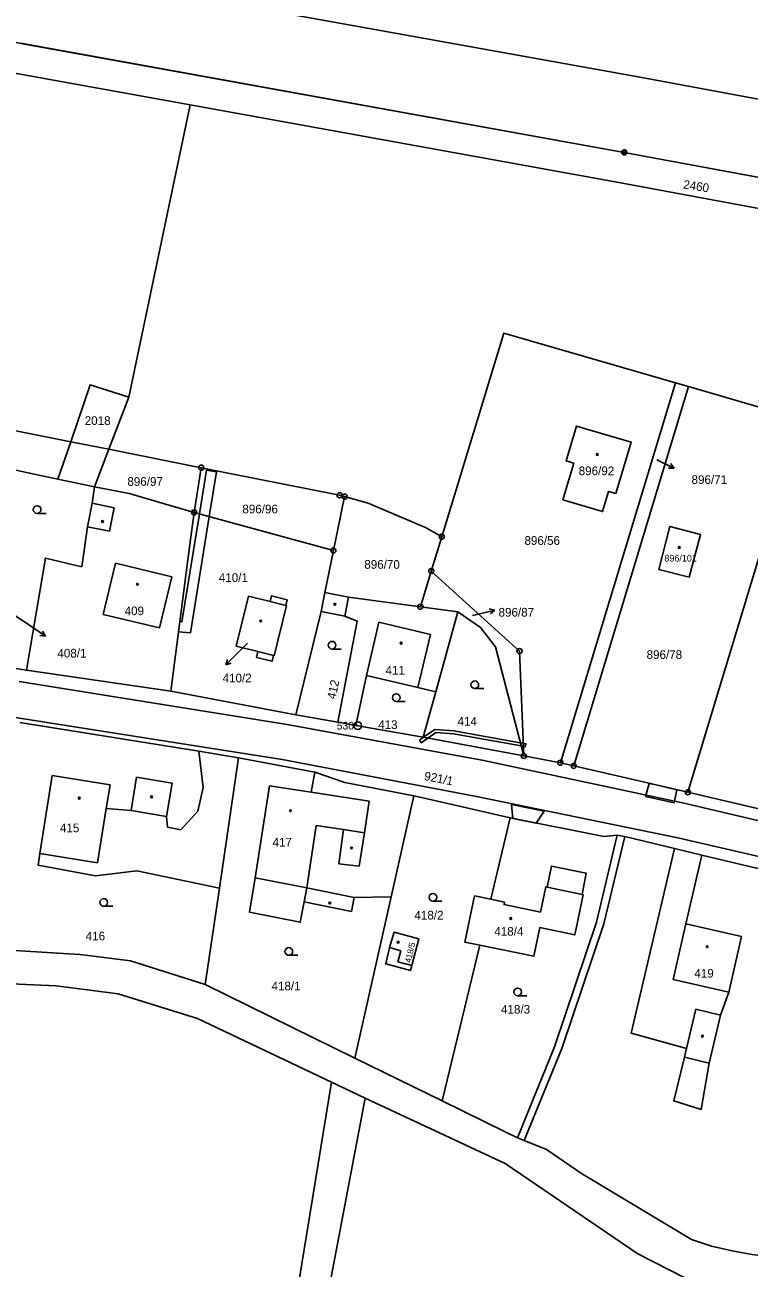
# Model space of a CAD drawing. Extents: x -504988 to -494607, y -1123820 to -1114018.
# Drawn here: x -500513.4 to -500371.7, y -1121156.5 to -1120913.2 of the extents above; entities that cross this region are included whole.
import ezdxf

# ---------------------------------------------------------------- set-up
doc = ezdxf.new("R2010")
doc.units = 0
for name, color, linetype in [('Hranice parcel', 7, 'Continuous'), ('Parcelní čísla', 7, 'Continuous'), ('Pop  PČ popisy', 7, 'Continuous'), ('Poz předměty', 7, 'Continuous'), ('Vnitřní kresba', 7, 'Continuous'), ('Věcná břemena k části', 7, 'Continuous'), ('Značky bodu BP', 7, 'Continuous'), ('Značky budov', 7, 'Continuous'), ('Značky kultur', 7, 'Continuous')]:
    doc.layers.add(name, color=color, linetype=linetype)

msp = doc.modelspace()

# ---------------------------------------------------------------- linework, layer by layer
at = {"layer": 'Hranice parcel'}
for p, q in [((-500493.12, -1120986.11), (-500481.13, -1120928.92)), ((-500386.18, -1120983.28), (-500408.67, -1121057.62)), ((-500383.63, -1120984.02), (-500386.18, -1120983.28)), ((-500497.01, -1120996.29), (-500493.12, -1120986.11)), ((-500406.06, -1121058.23), (-500383.63, -1120984.02)), ((-500361.67, -1120990.39), (-500383.63, -1120984.02)), ((-500383.73, -1121063.41), (-500361.67, -1120990.39)), ((-500504.48, -1120994.81), (-500506.98, -1121002.13)), ((-500504.48, -1120994.81), (-500497.01, -1120996.29)), ((-500499.83, -1121003.66), (-500497.01, -1120996.29)), ((-500478.93, -1120999.89), (-500497.01, -1120996.29)), ((-500478.93, -1120999.89), (-500480.34, -1121008.65)), ((-500450.89, -1121005.56), (-500453.08, -1121016.1)), ((-500446.3, -1121006.85), (-500450.89, -1121005.56)), ((-500453.08, -1121016.1), (-500480.34, -1121008.65)), ((-500431.88, -1121013.39), (-500433.93, -1121020.12)), ((-500454.75, -1121024.31), (-500453.08, -1121016.1)), ((-500433.93, -1121020.12), (-500436.05, -1121027.1)), ((-500433.93, -1121020.12), (-500416.66, -1121035.78)), ((-500455.46, -1121028.02), (-500454.75, -1121024.31)), ((-500436.05, -1121027.1), (-500428.72, -1121028.09)), ((-500460.42, -1121048.25), (-500455.46, -1121028.02)), ((-500433.07, -1121043.73), (-500428.72, -1121028.09)), ((-500415.85, -1121056.28), (-500421.36, -1121034.93)), ((-500416.66, -1121035.78), (-500415.85, -1121056.28)), ((-500513.13, -1121039.51), (-500521.79, -1121038.18)), ((-500513.13, -1121039.51), (-500484.9, -1121043.64)), ((-500484.9, -1121043.64), (-500460.42, -1121048.25)), ((-500435.55, -1121052.61), (-500433.07, -1121043.73)), ((-500460.42, -1121048.25), (-500452.18, -1121049.69)), ((-500479.4, -1121055.39), (-500514.41, -1121049.75)), ((-500452.18, -1121049.69), (-500448.67, -1121050.31)), ((-500448.67, -1121050.31), (-500435.55, -1121052.61)), ((-500435.55, -1121052.61), (-500415.85, -1121056.28)), ((-500471.62, -1121056.64), (-500479.4, -1121055.39)), ((-500475.37, -1121082.19), (-500471.62, -1121056.64)), ((-500456.69, -1121059.44), (-500471.62, -1121056.64)), ((-500408.67, -1121057.62), (-500415.85, -1121056.28)), ((-500408.67, -1121057.62), (-500406.06, -1121058.23)), ((-500441.77, -1121083.84), (-500437.33, -1121064.12)), ((-500422.29, -1121084.33), (-500418.49, -1121068.4)), ((-500418.49, -1121068.4), (-500400.14, -1121072.06)), ((-500400.14, -1121072.06), (-500397.59, -1121071.79)), ((-500380.99, -1121075.69), (-500386.37, -1121074.4)), ((-500341.82, -1121085.07), (-500380.99, -1121075.69)), ((-500478.14, -1121101.05), (-500475.37, -1121082.19)), ((-500427.34, -1121092.71), (-500425.48, -1121083.68)), ((-500425.48, -1121083.68), (-500422.29, -1121084.33)), ((-500448.9, -1121115.46), (-500441.77, -1121083.84)), ((-500422.29, -1121084.33), (-500419.58, -1121084.88)), ((-500431.83, -1121123.81), (-500424.46, -1121093.31)), ((-500424.46, -1121093.31), (-500427.34, -1121092.71)), ((-500413.87, -1121095.5), (-500424.46, -1121093.31)), ((-500448.9, -1121115.46), (-500431.83, -1121123.81)), ((-500469.81, -1121219.81), (-500453.45, -1121120.1)), ((-500453.45, -1121120.1), (-500446.85, -1121123.24)), ((-500446.85, -1121123.24), (-500465.32, -1121220.56))]:
    msp.add_line(p, q, dxfattribs=at)
for points in [[(-500764.98, -1120898.32), (-500631.41, -1120885.98), (-500618.26, -1120885.7), (-500608.56, -1120886.58), (-500597.08, -1120888.85), (-500587.15, -1120891.94), (-500532.37, -1120912.08), (-500524.35, -1120914.64), (-500516.15, -1120916.5), (-500513.53, -1120917), (-500396.19, -1120938.19), (-500282.34, -1120959.31), (-500275.43, -1120961.08), (-500094.63, -1121020.61), (-499913.83, -1121080.14), (-499909.87, -1121081.53), (-499905.97, -1121083.08), (-499793.8, -1121130.28), (-499791.45, -1121131.2), (-499789.49, -1121131.83)], [(-500481.13, -1120928.92), (-500517.21, -1120922.4), (-500525.93, -1120920.43), (-500534.44, -1120917.72), (-500589.22, -1120897.57), (-500597.01, -1120895.29), (-500604.68, -1120893.47), (-500611.82, -1120892.14), (-500620.47, -1120890.99)], [(-500275.13, -1120945.54), (-500279.36, -1120944.61), (-500393.48, -1120923.43), (-500512.84, -1120901.87), (-500515.38, -1120901.3)], [(-500481.13, -1120928.92), (-500397.25, -1120944.09), (-500283.44, -1120965.21), (-500278.08, -1120966.53), (-500138.09, -1121012.62)], [(-500386.18, -1120983.28), (-500419.74, -1120973.55), (-500431.88, -1121013.39)], [(-500561.67, -1120980.8), (-500539.74, -1120987.79), (-500504.48, -1120994.81)], [(-500504.48, -1120994.81), (-500500.68, -1120983.67), (-500493.12, -1120986.11)], [(-500397.82, -1121004.97), (-500399.24, -1121004.55), (-500400.41, -1121008.49), (-500408.18, -1121006.18), (-500406.07, -1120999), (-500407.51, -1120998.57), (-500405.49, -1120991.74), (-500394.82, -1120994.88), (-500397.82, -1121004.97)], [(-500506.98, -1121002.13), (-500512.53, -1121000.94), (-500516.66, -1121000.06)], [(-500450.89, -1121005.56), (-500451.86, -1121005.28), (-500478.93, -1120999.89)], [(-500499.83, -1121003.66), (-500500.29, -1121006.85), (-500501.21, -1121011.47), (-500502.32, -1121019.29), (-500509.4, -1121017.57), (-500513.13, -1121039.51)], [(-500480.34, -1121008.65), (-500493.03, -1121004.96), (-500499.83, -1121003.66)], [(-500431.88, -1121013.39), (-500434.93, -1121011.64), (-500446.3, -1121006.85)], [(-500484.9, -1121043.64), (-500481.16, -1121014.93), (-500480.34, -1121008.65)], [(-500383.49, -1121021.34), (-500389.44, -1121019.8), (-500387.23, -1121011.39), (-500381.27, -1121012.96), (-500383.49, -1121021.34)], [(-500462.1, -1121025.73), (-500462.37, -1121026.84), (-500462.23, -1121026.88), (-500464.67, -1121036.69), (-500464.8, -1121036.65), (-500465.08, -1121037.77), (-500468.14, -1121037.02), (-500467.87, -1121035.86), (-500472.09, -1121034.84), (-500469.68, -1121025.06), (-500465.44, -1121026.08), (-500465.16, -1121024.95), (-500462.1, -1121025.73)], [(-500436.05, -1121027.1), (-500450.12, -1121025.2), (-500454.75, -1121024.31)], [(-500455.46, -1121028.02), (-500450.82, -1121028.92), (-500448.4, -1121029.91), (-500452.18, -1121049.69)], [(-500421.36, -1121034.93), (-500424.29, -1121031.16), (-500428.72, -1121028.09)], [(-500448.67, -1121050.31), (-500446.61, -1121040.56), (-500436.54, -1121042.92), (-500433.07, -1121043.73)], [(-500479.4, -1121055.39), (-500478.53, -1121062.5), (-500479.58, -1121067.09), (-500482.94, -1121070.75), (-500485.53, -1121070.22), (-500485.71, -1121068.13), (-500484.65, -1121061.59), (-500491.58, -1121060.46), (-500492.64, -1121067), (-500497.52, -1121066.6), (-500496.78, -1121061.97), (-500508.07, -1121060.15), (-500510.53, -1121075.4), (-500510.85, -1121077.64), (-500499.6, -1121079.78), (-500491.56, -1121078.76), (-500475.37, -1121082.19)], [(-500406.06, -1121058.23), (-500389.93, -1121061.97), (-500383.73, -1121063.41)], [(-500456.69, -1121059.44), (-500457.41, -1121063.38), (-500465.55, -1121062.13), (-500468.41, -1121080.12), (-500469.48, -1121086.87), (-500459.55, -1121088.85), (-500458.83, -1121084.85), (-500449.57, -1121086.73), (-500449.01, -1121084), (-500441.77, -1121083.84)], [(-500437.33, -1121064.12), (-500450.85, -1121061.52), (-500456.69, -1121059.44)], [(-500437.33, -1121064.12), (-500435.84, -1121064.41), (-500418.49, -1121068.4)], [(-500383.73, -1121063.41), (-500365.68, -1121067.62), (-500361.28, -1121068.59)], [(-500417.04, -1121131.03), (-500409.84, -1121113.22), (-500401.6, -1121088.85), (-500397.59, -1121071.79)], [(-500386.37, -1121074.4), (-500396.06, -1121072.08), (-500397.59, -1121071.79)], [(-500386.37, -1121074.4), (-500394.82, -1121110.53), (-500384, -1121113.54), (-500384.41, -1121115.22), (-500386.48, -1121123.8), (-500381.12, -1121125.46), (-500379.59, -1121116.38), (-500377.34, -1121107.02), (-500375.74, -1121102.5), (-500373.26, -1121091.63), (-500384.13, -1121089.15), (-500380.99, -1121075.69)], [(-500419.58, -1121084.88), (-500419.68, -1121085.38), (-500412.57, -1121086.84), (-500411.55, -1121081.93), (-500411.28, -1121081.98), (-500410.44, -1121077.85), (-500403.6, -1121079.25), (-500404.43, -1121083.41), (-500404.22, -1121083.45), (-500405.86, -1121091.3), (-500412.7, -1121089.88), (-500413.87, -1121095.5)], [(-500437.75, -1121097.29), (-500438.02, -1121098.29), (-500442.83, -1121096.98), (-500442.08, -1121093.76), (-500441.22, -1121090.81), (-500439.03, -1121091.34), (-500436.34, -1121092.07), (-500437.75, -1121097.29)], [(-500520.79, -1121094.02), (-500502.67, -1121095.18), (-500501.61, -1121095.25), (-500492.78, -1121096.41), (-500478.14, -1121101.05)], [(-500453.45, -1121120.1), (-500479.67, -1121107.66), (-500495.2, -1121102.84), (-500507.32, -1121101.3), (-500520.55, -1121100.68), (-500557.7, -1121101.61), (-500589.02, -1121105.86), (-500602.59, -1121106.82), (-500624.72, -1121106.08), (-500646.33, -1121106.76), (-500655.09, -1121112.32), (-500660.29, -1121119.96), (-500660.92, -1121120.88), (-500668.64, -1121133.13), (-500674.71, -1121144.91), (-500681.84, -1121162.26), (-500689.12, -1121188.67)], [(-500478.14, -1121101.05), (-500452.75, -1121113.56), (-500448.9, -1121115.46)], [(-500093.53, -1121309.79), (-500096.64, -1121297.58), (-500125.14, -1121250.31), (-500143.37, -1121221.49), (-500154.49, -1121207.58), (-500171.25, -1121193.24), (-500179.79, -1121189.25), (-500191.69, -1121184.83), (-500210.15, -1121179.42), (-500240.92, -1121170.5), (-500265.19, -1121164.1), (-500289.32, -1121158.74), (-500305.17, -1121156.16), (-500321.82, -1121158.18), (-500359.14, -1121160.88), (-500369.12, -1121161.84), (-500376.67, -1121161), (-500384.33, -1121158.44), (-500393.5, -1121153.73), (-500419.45, -1121136.05), (-500446.85, -1121123.24)], [(-500431.83, -1121123.81), (-500419.48, -1121129.84), (-500417.04, -1121131.03)], [(-500417.04, -1121131.03), (-500415.78, -1121131.53), (-500411.36, -1121133.29), (-500404.51, -1121137.98), (-500383.05, -1121150.93), (-500379.09, -1121152.23), (-500375.08, -1121153.13), (-500371.2, -1121153.85), (-500367.89, -1121154.23), (-500362.33, -1121154.85), (-500358.56, -1121155.1)]]:
    msp.add_lwpolyline(points, dxfattribs=at)
at = {"layer": 'Pop  PČ popisy'}
for p, q in [((-500389.83, -1120998.31), (-500389.13, -1120998.65)), ((-500389.13, -1120998.65), (-500386.43, -1120999.97)), ((-500386.43, -1120999.97), (-500387.55, -1120999.98)), ((-500386.43, -1120999.97), (-500387.11, -1120999.08)), ((-500421.5, -1121027.8), (-500422.58, -1121027.54)), ((-500515.83, -1121028.51), (-500511.9, -1121031.19)), ((-500425.89, -1121028.82), (-500424.42, -1121028.48)), ((-500424.42, -1121028.48), (-500421.5, -1121027.8)), ((-500421.5, -1121027.8), (-500422.36, -1121028.52)), ((-500511.9, -1121031.19), (-500509.41, -1121032.87)), ((-500509.41, -1121032.87), (-500509.96, -1121031.89)), ((-500509.41, -1121032.87), (-500510.52, -1121032.72)), ((-500469.88, -1121034.25), (-500472.01, -1121036.35)), ((-500472.01, -1121036.35), (-500474.13, -1121038.47)), ((-500474.13, -1121038.47), (-500473.78, -1121037.41)), ((-500474.13, -1121038.47), (-500473.07, -1121038.12))]:
    msp.add_line(p, q, dxfattribs=at)
at = {"layer": 'Poz předměty'}
for p, q in [((-500514.25, -1120916.84), (-500396.18, -1120938.19)), ((-500396.18, -1120938.19), (-500278.83, -1120959.96))]:
    msp.add_line(p, q, dxfattribs=at)
for radius in [0.5, 0.4, 0.3, 0.2, 0.1]:
    msp.add_circle((-500396.18, -1120938.19), radius, dxfattribs=at)
at = {"layer": 'Vnitřní kresba'}
for p, q in [((-500499.83, -1121003.66), (-500506.98, -1121002.13)), ((-500500.29, -1121006.85), (-500495.94, -1121007.72)), ((-500495.94, -1121007.72), (-500496.86, -1121012.34)), ((-500496.86, -1121012.34), (-500501.21, -1121011.47)), ((-500498.11, -1121028.59), (-500495.7, -1121018.59)), ((-500495.7, -1121018.59), (-500484.72, -1121021.24)), ((-500484.72, -1121021.24), (-500487.13, -1121031.23)), ((-500450.12, -1121025.2), (-500450.82, -1121028.92)), ((-500465.44, -1121026.08), (-500462.37, -1121026.84)), ((-500487.13, -1121031.23), (-500498.11, -1121028.59)), ((-500446.61, -1121040.56), (-500444.18, -1121030.15)), ((-500444.18, -1121030.15), (-500434.11, -1121032.51)), ((-500434.11, -1121032.51), (-500436.54, -1121042.92)), ((-500467.87, -1121035.86), (-500464.8, -1121036.65)), ((-500514.53, -1121041.74), (-500462.1, -1121050.16)), ((-500463.1, -1121056.99), (-500516.96, -1121048.51)), ((-500462.1, -1121050.16), (-500423.67, -1121057.16)), ((-500425.1, -1121064.21), (-500463.1, -1121056.99)), ((-500423.67, -1121057.16), (-500384.2, -1121065.61)), ((-500457.41, -1121063.38), (-500446.05, -1121065.12)), ((-500385.7, -1121072.34), (-500425.1, -1121064.21)), ((-500497.52, -1121066.6), (-500499.23, -1121077.22)), ((-500446.05, -1121065.12), (-500447.01, -1121071.31)), ((-500384.2, -1121065.61), (-500347.24, -1121074.26)), ((-500485.71, -1121068.13), (-500492.64, -1121067)), ((-500456.42, -1121069.91), (-500458.28, -1121082.13)), ((-500451.11, -1121070.7), (-500456.42, -1121069.91)), ((-500451.99, -1121077.39), (-500451.11, -1121070.7)), ((-500447.01, -1121071.31), (-500451.11, -1121070.7)), ((-500447.01, -1121071.31), (-500448.02, -1121077.88)), ((-500396.06, -1121072.08), (-500400.18, -1121089.15)), ((-500348.68, -1121080.83), (-500385.7, -1121072.34)), ((-500499.23, -1121077.22), (-500510.53, -1121075.4)), ((-500448.02, -1121077.88), (-500451.99, -1121077.39)), ((-500458.28, -1121082.13), (-500468.41, -1121080.12)), ((-500458.83, -1121084.85), (-500458.28, -1121082.13)), ((-500458.28, -1121082.13), (-500449.01, -1121084)), ((-500411.28, -1121081.98), (-500404.43, -1121083.41)), ((-500400.18, -1121089.15), (-500408.42, -1121113.53)), ((-500386.61, -1121100.02), (-500384.13, -1121089.15)), ((-500442.08, -1121093.76), (-500439.91, -1121094.4)), ((-500439.91, -1121094.4), (-500440.45, -1121096.56)), ((-500440.45, -1121096.56), (-500437.75, -1121097.29)), ((-500375.74, -1121102.5), (-500386.61, -1121100.02)), ((-500384, -1121113.54), (-500382.15, -1121105.86)), ((-500382.15, -1121105.86), (-500377.34, -1121107.02)), ((-500408.42, -1121113.53), (-500415.78, -1121131.53)), ((-500379.59, -1121116.38), (-500384.41, -1121115.22))]:
    msp.add_line(p, q, dxfattribs=at)
at = {"layer": 'Věcná břemena k části'}
for points in [[(-500477.92, -1121000.38), (-500479.3, -1121008.93), (-500482.73, -1121030.06), (-500483.13, -1121030.02), (-500483.38, -1121032.01), (-500481.05, -1121032.22), (-500477.36, -1121009.46), (-500475.94, -1121000.7)], [(-500435.42, -1121052.63), (-500434.59, -1121052.79), (-500433.04, -1121051.72), (-500429.56, -1121051.95), (-500416.35, -1121054.35), (-500415.92, -1121054.43), (-500415.95, -1121053.82), (-500416.51, -1121053.71), (-500429.49, -1121051.35), (-500433.21, -1121051.11)], [(-500436.24, -1121053.21), (-500435.9, -1121053.7), (-500434.59, -1121052.79), (-500435.42, -1121052.63)], [(-500415.92, -1121054.43), (-500415.54, -1121054.5), (-500415.43, -1121053.91), (-500415.95, -1121053.82)], [(-500391.99, -1121064.25), (-500386.43, -1121065.47), (-500385.9, -1121062.91), (-500389.93, -1121061.97), (-500391.28, -1121061.66)], [(-500417.95, -1121068.51), (-500413.4, -1121069.42), (-500411.86, -1121067.07), (-500418.23, -1121065.77)]]:
    msp.add_lwpolyline(points, close=True, dxfattribs=at)
at = {"layer": 'Značky bodu BP'}
for centre, radius in [((-500478.93, -1120999.89), 0.5), ((-500478.93, -1120999.89), 0.0303), ((-500451.86, -1121005.28), 0.5), ((-500451.86, -1121005.28), 0.0303), ((-500450.89, -1121005.56), 0.5), ((-500450.89, -1121005.56), 0.0303), ((-500480.34, -1121008.65), 0.5), ((-500480.34, -1121008.65), 0.0303), ((-500431.88, -1121013.39), 0.5), ((-500453.08, -1121016.1), 0.5), ((-500431.88, -1121013.39), 0.0303), ((-500453.08, -1121016.1), 0.0303), ((-500433.93, -1121020.12), 0.5), ((-500433.93, -1121020.12), 0.0303), ((-500436.05, -1121027.1), 0.5), ((-500436.05, -1121027.1), 0.0303), ((-500416.66, -1121035.78), 0.5), ((-500416.66, -1121035.78), 0.0303), ((-500448.31, -1121050.37), 0.75), ((-500448.31, -1121050.37), 0.03), ((-500415.85, -1121056.28), 0.5), ((-500415.85, -1121056.28), 0.0303), ((-500408.67, -1121057.62), 0.5), ((-500408.67, -1121057.62), 0.0303), ((-500406.06, -1121058.23), 0.5), ((-500406.06, -1121058.23), 0.0303), ((-500383.73, -1121063.41), 0.5), ((-500383.73, -1121063.41), 0.0303)]:
    msp.add_circle(centre, radius, dxfattribs=at)
at = {"layer": 'Značky budov'}
for centre in [(-500401.45, -1120997.31), (-500498.26, -1121010.41), (-500385.41, -1121015.51), (-500491.42, -1121022.71), (-500452.79, -1121026.61), (-500467.3, -1121029.89), (-500439.83, -1121034.23), (-500488.65, -1121064.29), (-500502.8, -1121064.55), (-500461.49, -1121067), (-500449.53, -1121074.31), (-500453.78, -1121085.09), (-500418.39, -1121088.11), (-500440.41, -1121092.76), (-500379.94, -1121093.62), (-500380.88, -1121111.12)]:
    msp.add_circle(centre, 0.175, dxfattribs=at)
at = {"layer": 'Značky kultur'}
for p, q in [((-500511.04, -1121008.83), (-500509.29, -1121008.83)), ((-500453.34, -1121035.37), (-500451.59, -1121035.37)), ((-500425.41, -1121043.12), (-500423.66, -1121043.12)), ((-500440.79, -1121045.62), (-500439.04, -1121045.62)), ((-500498.01, -1121085.72), (-500496.26, -1121085.72)), ((-500433.61, -1121084.71), (-500431.86, -1121084.71)), ((-500461.8, -1121095.31), (-500460.05, -1121095.31)), ((-500417.01, -1121103.22), (-500415.26, -1121103.22))]:
    msp.add_line(p, q, dxfattribs=at)
for centre in [(-500511.04, -1121008.08), (-500453.34, -1121034.62), (-500425.41, -1121042.37), (-500440.79, -1121044.87), (-500433.61, -1121083.96), (-500498.01, -1121084.97), (-500461.8, -1121094.56), (-500417.01, -1121102.47)]:
    msp.add_circle(centre, 0.75, dxfattribs=at)

# ---------------------------------------------------------------- texts
at = {"layer": 'Parcelní čísla'}
for s, height, rotation, p in [('2460', 1.7, 351, (-500384.72, -1120945.24)), ('412', 1.7, 78, (-500452.68, -1121045.31)), ('921/1', 1.7, 349, (-500435.42, -1121060.99)), ('418/5', 1.2, 77, (-500437.95, -1121096.86))]:
    msp.add_text(s, height=height, rotation=rotation, dxfattribs=at).set_placement(p)
for s, height, p in [('2018', 1.7, (-500501.73, -1120991.53)), ('896/92', 1.7, (-500405.09, -1121001.36)), ('896/97', 1.7, (-500493.39, -1121003.44)), ('896/71', 1.7, (-500383.01, -1121003.08)), ('896/96', 1.7, (-500470.89, -1121008.83)), ('896/56', 1.7, (-500415.7, -1121014.99)), ('896/70', 1.7, (-500447.03, -1121019.67)), ('896/101', 1.309, (-500388.32, -1121018.26)), ('410/1', 1.7, (-500475.5, -1121022.24)), ('409', 1.7, (-500493.93, -1121028.76)), ('896/87', 1.7, (-500420.77, -1121029.03)), ('408/1', 1.7, (-500507.08, -1121037.04)), ('896/78', 1.7, (-500391.81, -1121037.32)), ('411', 1.7, (-500442.89, -1121040.38)), ('410/2', 1.7, (-500474.76, -1121041.9)), ('413', 1.7, (-500444.32, -1121051.03)), ('414', 1.7, (-500428.8, -1121050.35)), ('415', 1.7, (-500506.58, -1121071.22)), ('417', 1.7, (-500464.99, -1121074.02)), ('418/2', 1.7, (-500437.23, -1121088.3)), ('416', 1.7, (-500501.54, -1121092.39)), ('418/4', 1.7, (-500421.6, -1121091.47)), ('419', 1.7, (-500382.46, -1121099.67)), ('418/1', 1.7, (-500465.19, -1121102.16)), ('418/3', 1.7, (-500420.28, -1121106.72))]:
    msp.add_text(s, height=height, dxfattribs=at).set_placement(p)
at = {"layer": 'Značky bodu BP'}
msp.add_text('530', height=1.5, dxfattribs=at).set_placement((-500452.41, -1121051.12))

doc.saveas('drawing.dxf')
